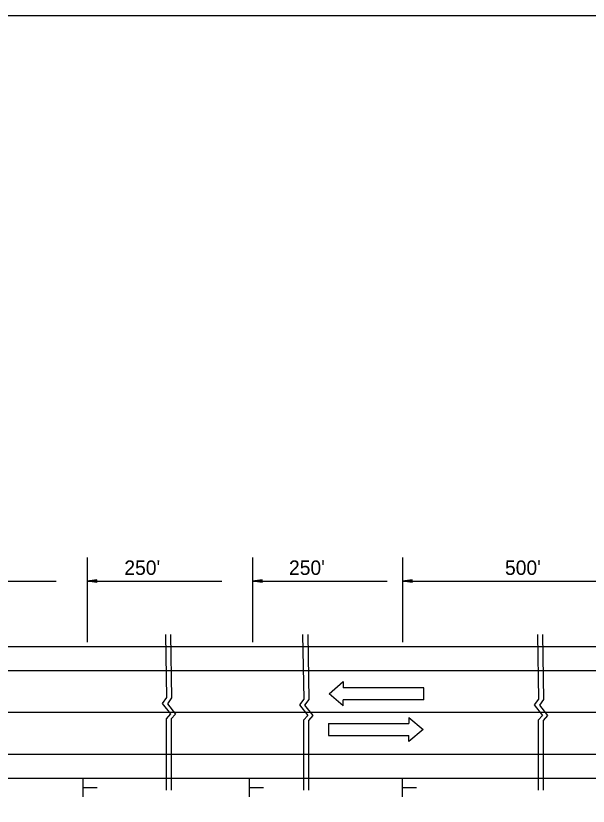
# Model space of a CAD drawing. Extents: x 1807779 to 1818251, y 673292 to 678849.
# Drawn here: x 1811171.6 to 1811403.2, y 677059.3 to 677378.9 of the extents above; entities that cross this region are included whole.
import ezdxf

# ---------------------------------------------------------------- set-up
doc = ezdxf.new("R2010")
doc.units = 0
for name, color, linetype in [('Default', 7, 'Continuous'), ('DSN_DRFT_Guideline-No-Plot', 7, 'Continuous'), ('R_MOT', 7, 'Continuous')]:
    doc.layers.add(name, color=color, linetype=linetype)

msp = doc.modelspace()

# ---------------------------------------------------------------- linework, layer by layer
at = {"layer": 'Default'}
for p, q in [((1811200.45, 677159.82), (1811200.45, 677125.58)), ((1811267.41, 677159.82), (1811267.41, 677125.58)), ((1811328.06, 677159.82), (1811328.06, 677125.58)), ((1811133.48, 677150.3), (1811187.95, 677150.3)), ((1811204.36, 677150.84), (1811200.45, 677150.3)), ((1811200.45, 677150.3), (1811254.92, 677150.3)), ((1811204.36, 677149.75), (1811200.45, 677150.3)), ((1811204.36, 677150.75), (1811201.1, 677150.3)), ((1811204.36, 677149.84), (1811201.1, 677150.3)), ((1811204.36, 677150.66), (1811201.78, 677150.3)), ((1811204.36, 677149.93), (1811201.78, 677150.3)), ((1811204.36, 677150.57), (1811202.43, 677150.3)), ((1811204.36, 677150.02), (1811202.43, 677150.3)), ((1811204.36, 677150.47), (1811203.09, 677150.3)), ((1811204.36, 677150.12), (1811203.09, 677150.3)), ((1811204.36, 677150.38), (1811203.74, 677150.3)), ((1811204.36, 677150.21), (1811203.74, 677150.3)), ((1811204.36, 677149.75), (1811204.36, 677150.84)), ((1811271.33, 677150.84), (1811267.41, 677150.3)), ((1811267.41, 677150.3), (1811321.88, 677150.3)), ((1811271.33, 677149.75), (1811267.41, 677150.3)), ((1811271.33, 677150.75), (1811268.07, 677150.3)), ((1811271.33, 677149.84), (1811268.07, 677150.3)), ((1811271.33, 677150.66), (1811268.74, 677150.3)), ((1811271.33, 677149.93), (1811268.74, 677150.3)), ((1811271.33, 677150.57), (1811269.39, 677150.3)), ((1811271.33, 677150.02), (1811269.39, 677150.3)), ((1811271.33, 677150.47), (1811270.06, 677150.3)), ((1811271.33, 677150.12), (1811270.06, 677150.3)), ((1811271.33, 677150.38), (1811270.71, 677150.3)), ((1811271.33, 677150.21), (1811270.71, 677150.3)), ((1811271.33, 677149.75), (1811271.33, 677150.84)), ((1811331.97, 677150.84), (1811328.06, 677150.3)), ((1811328.06, 677150.3), (1811422.76, 677150.3)), ((1811331.97, 677149.75), (1811328.06, 677150.3)), ((1811331.97, 677150.75), (1811328.71, 677150.3)), ((1811331.97, 677149.84), (1811328.71, 677150.3)), ((1811331.97, 677150.66), (1811329.38, 677150.3)), ((1811331.97, 677149.93), (1811329.38, 677150.3)), ((1811331.97, 677150.57), (1811330.03, 677150.3)), ((1811331.97, 677150.02), (1811330.03, 677150.3)), ((1811331.97, 677150.47), (1811330.7, 677150.3)), ((1811331.97, 677150.12), (1811330.7, 677150.3)), ((1811331.97, 677150.38), (1811331.35, 677150.3)), ((1811331.97, 677150.21), (1811331.35, 677150.3)), ((1811331.97, 677149.75), (1811331.97, 677150.84)), ((1810973.55, 677123.92), (1812078.15, 677123.92)), ((1810973.55, 677114.2), (1811546.29, 677114.2)), ((1810973.55, 677097.29), (1811428.93, 677097.29)), ((1810973.55, 677080.38), (1811546.29, 677080.38)), ((1810973.55, 677070.66), (1812078.15, 677070.66)), ((1811198.79, 677063.05), (1811198.79, 677070.66)), ((1811266.09, 677063.05), (1811266.09, 677070.66)), ((1811328.06, 677063.05), (1811328.06, 677070.66)), ((1811198.91, 677066.83), (1811204.49, 677066.83)), ((1811266.21, 677066.83), (1811271.79, 677066.83)), ((1811328.18, 677066.83), (1811333.75, 677066.83))]:
    msp.add_line(p, q, dxfattribs=at)
for points in [[(1811232.11, 677128.79), (1811232.53, 677103.18), (1811230.83, 677100.83), (1811234.14, 677096.62), (1811232.4, 677094.68), (1811232.39, 677065.8)], [(1811234.19, 677128.79), (1811234.61, 677103.1), (1811232.92, 677100.75), (1811236.22, 677096.54), (1811234.48, 677094.6), (1811234.48, 677065.8)], [(1811287.65, 677128.79), (1811288.08, 677102.57), (1811286.38, 677100.22), (1811289.69, 677096.01), (1811287.95, 677094.07), (1811287.94, 677065.8)], [(1811289.73, 677128.79), (1811290.16, 677102.49), (1811288.47, 677100.14), (1811291.77, 677095.93), (1811290.03, 677093.98), (1811290.03, 677065.8)], [(1811382.68, 677128.79), (1811383.1, 677102.57), (1811381.41, 677100.22), (1811384.71, 677096.01), (1811382.97, 677094.07), (1811382.97, 677065.8)], [(1811384.76, 677128.79), (1811385.19, 677102.49), (1811383.49, 677100.14), (1811386.8, 677095.93), (1811385.06, 677093.98), (1811385.05, 677065.8)]]:
    msp.add_lwpolyline(points, dxfattribs=at)
at = {"layer": 'DSN_DRFT_Guideline-No-Plot'}
msp.add_lwpolyline([(1810700.85, 676379.88), (1812350.85, 676379.88), (1812350.85, 677378.94), (1810700.85, 677378.94)], close=True, dxfattribs=at)
at = {"layer": 'R_MOT'}
for p, q in [((1811298.37, 677104.78), (1811304.1, 677109.65)), ((1811304.1, 677109.65), (1811304.1, 677107.21)), ((1811336.69, 677107.21), (1811304.1, 677107.21)), ((1811336.69, 677102.35), (1811336.69, 677107.21)), ((1811304.1, 677099.92), (1811298.37, 677104.78)), ((1811336.69, 677102.35), (1811304.1, 677102.35)), ((1811304.1, 677099.92), (1811304.1, 677102.35)), ((1811298.11, 677092.79), (1811330.69, 677092.79)), ((1811298.11, 677092.79), (1811298.11, 677087.93)), ((1811330.69, 677095.22), (1811336.42, 677090.36)), ((1811330.69, 677095.22), (1811330.69, 677092.79)), ((1811336.42, 677090.36), (1811330.69, 677085.5)), ((1811298.11, 677087.93), (1811330.69, 677087.93)), ((1811330.69, 677085.5), (1811330.69, 677087.93))]:
    msp.add_line(p, q, dxfattribs=at)

# ---------------------------------------------------------------- texts
at = {"layer": 'Default'}
for s, p in [("250'", (1811215.49, 677152.83)), ("250'", (1811282.13, 677152.83)), ("500'", (1811369.55, 677152.83))]:
    msp.add_text(s, height=5.835, dxfattribs=at).set_placement(p)

doc.saveas('drawing.dxf')
